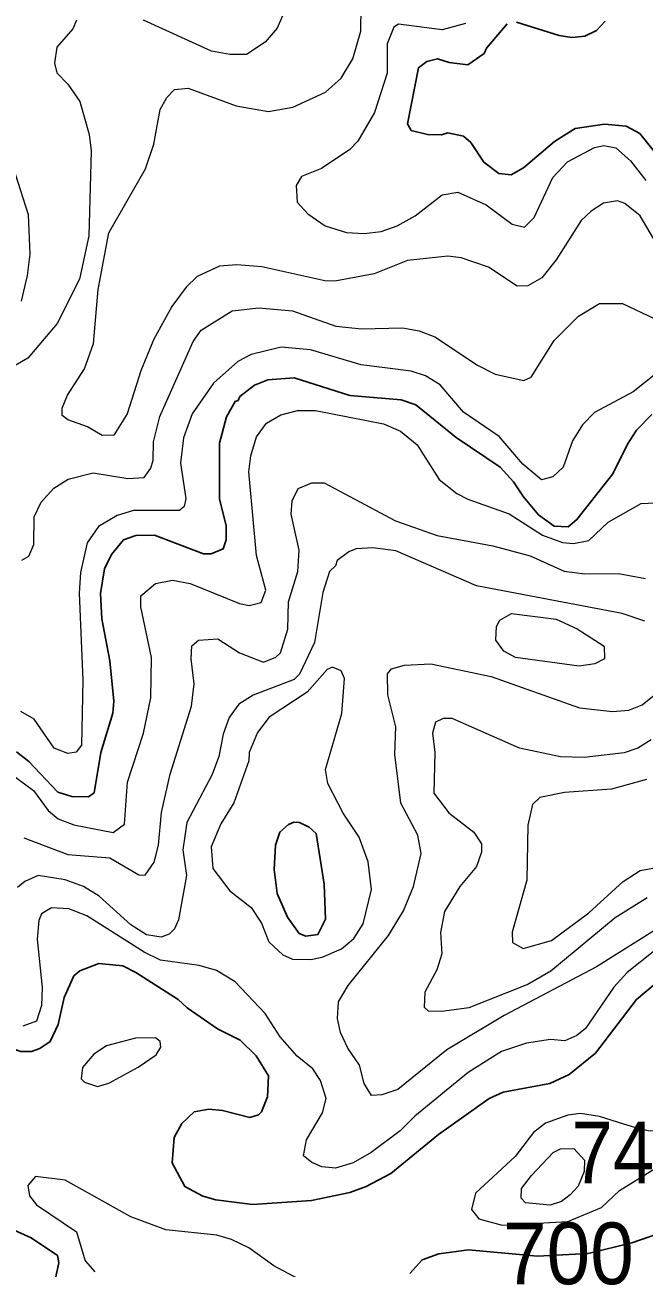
# Model space of a CAD drawing. Extents: x 673.3 to 698.5, y 6984.3 to 7012.3.
# Drawn here: x 674.508 to 675.31, y 6990.452 to 6992.064 of the extents above; entities that cross this region are included whole.
import ezdxf
from ezdxf.enums import TextEntityAlignment as Align

# ---------------------------------------------------------------- set-up
doc = ezdxf.new("R2010")
doc.units = 0
doc.header["$LTSCALE"] = 0.032
doc.layers.add('1', color=7, linetype='Continuous', lineweight=25)
doc.layers.add('2', color=7, linetype='Continuous', lineweight=13)
doc.layers.add('21', color=7, linetype='Continuous')
doc.layers.add('61', color=7, linetype='Continuous')

msp = doc.modelspace()

# ---------------------------------------------------------------- linework, layer by layer
at = {"layer": '1'}
for points in [[(675.1447, 6992.0675), (675.2002, 6992.05), (675.2165, 6992.0476), (675.2334, 6992.0493), (675.2485, 6992.0565), (675.2599, 6992.0686)], [(675.3485, 6991.8686), (675.3048, 6991.9228), (675.2868, 6991.9326), (675.2588, 6991.9351), (675.2211, 6991.9295), (675.1943, 6991.9125), (675.1538, 6991.8786), (675.1379, 6991.8692), (675.1221, 6991.871), (675.1027, 6991.8857), (675.0856, 6991.9115), (675.0764, 6991.9197), (675.0558, 6991.9237), (675.0477, 6991.9213), (675.0298, 6991.9215), (675.0086, 6991.9269), (675.0036, 6991.9357), (675.0181, 6992.0082), (675.0287, 6992.0162), (675.0425, 6992.0198), (675.0576, 6992.015), (675.0818, 6992.0119), (675.1028, 6992.0266), (675.1061, 6992.0336), (675.1328, 6992.0651)], [(674.622, 6991.1715), (674.623, 6991.187), (674.6182, 6991.2396), (674.6076, 6991.2937), (674.6061, 6991.3267), (674.611, 6991.3585), (674.6203, 6991.3774), (674.6356, 6991.3962), (674.6517, 6991.4017), (674.676, 6991.4025), (674.7395, 6991.3781), (674.7493, 6991.3781), (674.7649, 6991.3848), (674.7688, 6991.3961), (674.7688, 6991.4145), (674.76, 6991.4494), (674.76, 6991.5217), (674.769, 6991.5559), (674.7802, 6991.5757), (674.7842, 6991.5769), (674.7863, 6991.5819), (674.8055, 6991.5969), (674.8229, 6991.6037), (674.8568, 6991.6061), (674.9288, 6991.5833), (674.9956, 6991.5778), (675.0143, 6991.5714), (675.0667, 6991.5289), (675.1239, 6991.4904), (675.1412, 6991.4716), (675.1538, 6991.4518), (675.1734, 6991.4288), (675.1939, 6991.4139), (675.2119, 6991.4132), (675.2232, 6991.4226), (675.2699, 6991.4817), (675.2888, 6991.5204), (675.3003, 6991.5383), (675.3203, 6991.5588)], [(674.4969, 6991.1215), (674.5129, 6991.1088), (674.5505, 6991.0692), (674.5688, 6991.0637), (674.5905, 6991.063), (674.5976, 6991.0685), (674.6063, 6991.1205), (674.622, 6991.1715)], [(675.3569, 6990.8479), (675.3004, 6990.8004), (675.2471, 6990.7309), (675.2133, 6990.7034), (675.1879, 6990.6915), (675.1275, 6990.6802), (675.1096, 6990.6722), (675.0439, 6990.6252), (674.982, 6990.575), (674.9503, 6990.5582), (674.9288, 6990.5503), (674.8793, 6990.54), (674.8028, 6990.5345), (674.7552, 6990.5406), (674.7383, 6990.5455), (674.7154, 6990.5578), (674.6989, 6990.5889), (674.7012, 6990.6216), (674.7114, 6990.6396), (674.7271, 6990.6547), (674.7461, 6990.6581), (674.764, 6990.6565), (674.7995, 6990.6476), (674.8105, 6990.651), (674.8144, 6990.655), (674.8225, 6990.6741), (674.8234, 6990.7013), (674.8076, 6990.7276), (674.7867, 6990.7479), (674.7574, 6990.7624), (674.7182, 6990.7894), (674.7064, 6990.8002), (674.6519, 6990.8356), (674.635, 6990.8439), (674.6036, 6990.8471), (674.579, 6990.8376), (674.5714, 6990.831), (674.5587, 6990.8029), (674.5511, 6990.7682), (674.5405, 6990.746), (674.5272, 6990.7369), (674.5164, 6990.7331)], [(674.5164, 6990.7331), (674.5026, 6990.7331), (674.4804, 6990.7406), (674.4395, 6990.7608), (674.4056, 6990.7689), (674.3745, 6990.7681), (674.3636, 6990.7633), (674.3458, 6990.737), (674.3382, 6990.7184), (674.3391, 6990.6945), (674.3597, 6990.6728), (674.3742, 6990.6654), (674.4138, 6990.6572), (674.4224, 6990.6471), (674.426, 6990.6101), (674.4204, 6990.5589), (674.4387, 6990.5308), (674.4679, 6990.5131), (674.5162, 6990.4914), (674.5502, 6990.4687), (674.5521, 6990.4591), (674.5425, 6990.4155)], [(675.0069, 6990.4451), (675.0225, 6990.4628), (675.0444, 6990.4709), (675.0829, 6990.4757), (675.1719, 6990.4678), (675.2379, 6990.4713), (675.2942, 6990.4849), (675.343, 6990.502), (675.3637, 6990.5093), (675.3905, 6990.5282), (675.4394, 6990.5722), (675.467, 6990.5902), (675.5018, 6990.6036), (675.5396, 6990.602)]]:
    msp.add_lwpolyline(points, dxfattribs=at)
msp.add_lwpolyline([(674.8852, 6991.0156), (674.8763, 6991.0238), (674.8639, 6991.03), (674.8563, 6991.0303), (674.8493, 6991.0273), (674.8382, 6991.0173), (674.8325, 6991.0005), (674.8308, 6990.9689), (674.8347, 6990.9378), (674.8481, 6990.9071), (674.8635, 6990.8861), (674.8718, 6990.8823), (674.8877, 6990.8846), (674.8975, 6990.9044), (674.8959, 6990.9501)], close=True, dxfattribs=at)
at = {"layer": '2'}
for points in [[(674.658, 6991.6155), (674.6404, 6991.5594), (674.6231, 6991.5321), (674.6083, 6991.5313), (674.5891, 6991.5429), (674.5637, 6991.5516), (674.5564, 6991.5576), (674.5564, 6991.567), (674.5632, 6991.584), (674.585, 6991.6178), (674.5968, 6991.6507), (674.6028, 6991.7207), (674.6168, 6991.7944), (674.6641, 6991.877), (674.6752, 6991.909), (674.6832, 6991.954), (674.6919, 6991.9696), (674.7016, 6991.98), (674.7197, 6991.9816), (674.7816, 6991.9588), (674.8236, 6991.9514), (674.8552, 6991.957), (674.8975, 6991.9767), (674.9179, 6991.9945), (674.9327, 6992.0198), (674.9431, 6992.0556), (674.9438, 6992.0872)], [(674.8486, 6992.0914), (674.835, 6992.0595), (674.8191, 6992.0414), (674.7952, 6992.0256), (674.7737, 6992.0254), (674.7499, 6992.0299), (674.6617, 6992.0701)], [(674.575, 6992.07), (674.5699, 6992.0587), (674.5493, 6992.0348), (674.5465, 6992.0143), (674.5493, 6992.0017), (674.5638, 6991.987), (674.5791, 6991.9644), (674.5914, 6991.9218), (674.5937, 6991.9006), (674.5907, 6991.7903), (674.5787, 6991.7343), (674.5498, 6991.6768), (674.5118, 6991.6317), (674.4643, 6991.6045)], [(674.986, 6992.0609), (674.9774, 6992.0393), (674.9773, 6992.0013), (674.9608, 6991.9502), (674.9395, 6991.9129), (674.9289, 6991.9023), (674.8921, 6991.8778), (674.8665, 6991.8672), (674.8593, 6991.8557), (674.8608, 6991.834), (674.8745, 6991.8189), (674.8968, 6991.8033), (674.9248, 6991.7948), (674.9476, 6991.7934), (674.9696, 6991.7959), (674.9903, 6991.8031), (675.0135, 6991.8163), (675.0484, 6991.8435), (675.069, 6991.8471), (675.1054, 6991.8304), (675.1391, 6991.8054), (675.1554, 6991.8016), (675.1678, 6991.8143), (675.1919, 6991.8661), (675.211, 6991.8862), (675.2461, 6991.9049), (675.2582, 6991.9073), (675.2735, 6991.9042), (675.2926, 6991.8876), (675.3126, 6991.8621)], [(675.0787, 6992.0655), (675.0485, 6992.0573), (674.9919, 6992.0645), (674.986, 6992.0609)], [(674.5034, 6991.7057), (674.5114, 6991.739), (674.5147, 6991.7667), (674.5127, 6991.8177), (674.4959, 6991.8702)], [(675.3226, 6991.7869), (675.3053, 6991.8164), (675.2851, 6991.8324), (675.2757, 6991.8356), (675.2578, 6991.8325), (675.2418, 6991.8225), (675.2289, 6991.8102), (675.1963, 6991.7594), (675.1779, 6991.7358), (675.1595, 6991.7257), (675.1458, 6991.7251), (675.1087, 6991.7497), (675.0733, 6991.762), (675.0561, 6991.764), (675.0038, 6991.7584), (674.9605, 6991.7411), (674.9096, 6991.7316), (674.8964, 6991.732), (674.8148, 6991.7502), (674.7825, 6991.7526), (674.7602, 6991.751), (674.731, 6991.7376), (674.717, 6991.7238), (674.6982, 6991.6987), (674.6744, 6991.6557), (674.658, 6991.6155)], [(674.5039, 6991.3701), (674.5132, 6991.3752), (674.5195, 6991.3901), (674.5198, 6991.4261), (674.529, 6991.4449), (674.5453, 6991.4632), (674.5639, 6991.475), (674.5965, 6991.4832), (674.6415, 6991.4758), (674.6627, 6991.4772), (674.6712, 6991.4891), (674.6742, 6991.4997), (674.6744, 6991.5234), (674.6828, 6991.5562), (674.7258, 6991.6533), (674.7363, 6991.668), (674.7764, 6991.6929), (674.8112, 6991.6972), (674.8547, 6991.6929), (674.9107, 6991.6733), (674.9439, 6991.6696), (674.9973, 6991.6712), (675.019, 6991.6673), (675.039, 6991.6592), (675.0944, 6991.6225), (675.1171, 6991.6111), (675.1542, 6991.6029), (675.1639, 6991.6072), (675.1938, 6991.6547), (675.2252, 6991.6862), (675.2525, 6991.7025), (675.2821, 6991.7027), (675.3243, 6991.6827)], [(675.2175, 6991.5244), (675.2052, 6991.4903), (675.192, 6991.4781), (675.1775, 6991.4742), (675.1532, 6991.4945), (675.1223, 6991.5303), (675.0764, 6991.5617), (675.0462, 6991.5973), (675.0272, 6991.6089), (675.0086, 6991.615), (674.9435, 6991.6232), (674.878, 6991.6427), (674.8401, 6991.646), (674.8013, 6991.6367), (674.7838, 6991.6274), (674.7524, 6991.5993), (674.7249, 6991.5596), (674.7136, 6991.5286), (674.7095, 6991.4956), (674.7167, 6991.4497), (674.7143, 6991.4394), (674.7083, 6991.4343), (674.6487, 6991.4342), (674.6275, 6991.4278), (674.6033, 6991.4136), (674.5886, 6991.3922), (674.58, 6991.3539), (674.5783, 6991.3271), (674.5831, 6991.2142), (674.5815, 6991.13), (674.5742, 6991.1212), (674.5634, 6991.1192), (674.546, 6991.1264), (674.5198, 6991.1636), (674.5028, 6991.1739)], [(675.3255, 6991.6114), (675.296, 6991.5883), (675.2461, 6991.5612), (675.2305, 6991.5452), (675.2175, 6991.5244)], [(674.4959, 6991.0887), (674.5191, 6991.0715), (674.538, 6991.0452), (674.5511, 6991.0348), (674.5712, 6991.0267), (674.6224, 6991.0167), (674.637, 6991.0277), (674.6411, 6991.082), (674.6618, 6991.1456), (674.6712, 6991.1914), (674.672, 6991.2438), (674.6582, 6991.3093), (674.6583, 6991.3236), (674.6772, 6991.3398), (674.6992, 6991.3438), (674.7219, 6991.3396), (674.7861, 6991.3139), (674.7986, 6991.3113), (674.8139, 6991.315), (674.82, 6991.3312), (674.808, 6991.3761), (674.7982, 6991.4844), (674.8006, 6991.5051), (674.808, 6991.5297), (674.8211, 6991.5476), (674.8396, 6991.5583), (674.8612, 6991.5637), (674.8845, 6991.5637), (674.9728, 6991.5465), (674.9947, 6991.5371), (675.0162, 6991.5192), (675.0447, 6991.4744), (675.0675, 6991.4564), (675.0819, 6991.4488), (675.1356, 6991.43), (675.1786, 6991.4025), (675.2044, 6991.3926), (675.2189, 6991.3914), (675.2385, 6991.3952), (675.2635, 6991.4191), (675.3065, 6991.4432), (675.3335, 6991.4446)], [(674.5064, 6991.0098), (674.5637, 6990.9883), (674.6182, 6990.9839), (674.6558, 6990.9621), (674.6637, 6990.9616), (674.6753, 6990.9785), (674.6809, 6991.0003), (674.685, 6991.0428), (674.6964, 6991.0926), (674.724, 6991.1807), (674.7274, 6991.2098), (674.7233, 6991.2422), (674.7241, 6991.2588), (674.7329, 6991.2662), (674.758, 6991.2681), (674.7862, 6991.2496), (674.8172, 6991.2379), (674.8329, 6991.2443), (674.8392, 6991.2498), (674.8486, 6991.2803), (674.8494, 6991.3159), (674.8617, 6991.3552), (674.8633, 6991.3829), (674.8528, 6991.4295), (674.8541, 6991.447), (674.8622, 6991.463), (674.8799, 6991.4701), (674.8956, 6991.47), (674.9881, 6991.4207), (675.0422, 6991.4017), (675.1142, 6991.3886), (675.1627, 6991.3757), (675.2065, 6991.3558), (675.2336, 6991.352), (675.277, 6991.3528), (675.3119, 6991.346)], [(675.3113, 6991.2909), (675.2816, 6991.3007), (675.0931, 6991.3366), (674.9887, 6991.3821), (674.9587, 6991.3861), (674.9373, 6991.3846), (674.9278, 6991.3809), (674.9126, 6991.3693), (674.9103, 6991.3625), (674.9026, 6991.3552), (674.894, 6991.3281), (674.883, 6991.2631), (674.8638, 6991.2223), (674.857, 6991.2154), (674.8037, 6991.195), (674.7852, 6991.1834), (674.7728, 6991.166), (674.765, 6991.1445), (674.7594, 6991.1154), (674.7504, 6991.0921), (674.7177, 6991.0298), (674.7127, 6990.9946), (674.7175, 6990.9611), (674.7068, 6990.9038), (674.7019, 6990.8919), (674.6951, 6990.8849), (674.6847, 6990.8812), (674.6654, 6990.8843), (674.6454, 6990.8973), (674.6042, 6990.9344), (674.5839, 6990.9469), (674.5601, 6990.9554), (674.525, 6990.961), (674.5081, 6990.9535), (674.4986, 6990.9456)], [(674.995, 6991.055), (674.9872, 6991.118), (674.9887, 6991.1538), (674.9782, 6991.1953), (674.9776, 6991.2225), (674.9831, 6991.2289), (674.9996, 6991.234), (675.034, 6991.2356), (675.112, 6991.2189), (675.2265, 6991.1785), (675.2693, 6991.1737), (675.2906, 6991.1753), (675.3078, 6991.1825), (675.3277, 6991.1984)], [(675.3194, 6991.1371), (675.302, 6991.1263), (675.2842, 6991.12), (675.2324, 6991.1142), (675.2018, 6991.1151), (675.1487, 6991.1263), (675.0617, 6991.1646), (675.0501, 6991.1646), (675.0398, 6991.1601), (675.0359, 6991.1456), (675.0392, 6991.1204), (675.0377, 6991.068), (675.0571, 6991.0425), (675.0895, 6991.0175), (675.0995, 6991.0023), (675.0996, 6990.9912), (675.0929, 6990.9726), (675.0716, 6990.947), (675.0517, 6990.9145), (675.0466, 6990.8872), (675.048, 6990.8595), (675.0417, 6990.839), (675.0263, 6990.8101), (675.0254, 6990.7904), (675.0303, 6990.7859), (675.0479, 6990.7855), (675.0837, 6990.7902), (675.1589, 6990.8198), (675.1894, 6990.8375), (675.2726, 6990.9069), (675.314, 6990.9327)], [(675.3135, 6991.0858), (675.2678, 6991.0732), (675.2073, 6991.0687), (675.1751, 6991.0623), (675.1657, 6991.0532)], [(675.3503, 6990.9065), (675.2484, 6990.8426), (675.1291, 6990.7796), (675.0545, 6990.735), (674.991, 6990.6837), (674.9705, 6990.6768), (674.9571, 6990.6761), (674.9475, 6990.6917), (674.9415, 6990.7153), (674.9262, 6990.7374), (674.9169, 6990.7578), (674.9131, 6990.7759), (674.9145, 6990.7975), (674.9269, 6990.8185), (674.9791, 6990.8832), (674.9984, 6990.9154), (675.0116, 6990.9467), (675.0212, 6990.9897), (675.0171, 6991.0135), (674.995, 6991.055)], [(675.1657, 6991.0532), (675.1598, 6991.0265), (675.1582, 6990.9553), (675.1395, 6990.8878), (675.1398, 6990.8745), (675.1535, 6990.8667), (675.1901, 6990.877), (675.2385, 6990.9128), (675.283, 6990.9533), (675.3051, 6990.9676), (675.3451, 6990.9749)], [(674.565, 6990.918), (674.5423, 6990.9193), (674.5295, 6990.9113), (674.5261, 6990.9029), (674.5238, 6990.8785), (674.5302, 6990.8158), (674.5293, 6990.7926), (674.5231, 6990.7723), (674.5051, 6990.7658)], [(675.3243, 6990.8641), (675.2881, 6990.8353), (675.2709, 6990.8163), (675.2343, 6990.763), (675.2231, 6990.7539), (675.2075, 6990.747), (675.1891, 6990.7485), (675.1578, 6990.7436), (675.1255, 6990.7329), (675.0822, 6990.7058), (675.0132, 6990.6491), (674.9942, 6990.6303), (674.9565, 6990.6021), (674.9331, 6990.5888), (674.9106, 6990.5816), (674.8929, 6990.5833), (674.8797, 6990.589), (674.8691, 6990.5977), (674.8729, 6990.6183), (674.8935, 6990.6534), (674.8982, 6990.6722), (674.891, 6990.6956), (674.881, 6990.7105), (674.8606, 6990.7268), (674.8386, 6990.752), (674.8191, 6990.7822), (674.7805, 6990.8232), (674.7561, 6990.838), (674.7337, 6990.8445), (674.6837, 6990.8512), (674.6623, 6990.8619), (674.5881, 6990.9089), (674.565, 6990.918)], [(674.901, 6990.4174), (674.8305, 6990.455), (674.798, 6990.4783), (674.7757, 6990.4894), (674.7565, 6990.4951), (674.6904, 6990.5018), (674.6451, 6990.5189), (674.5602, 6990.5661), (674.5217, 6990.571), (674.5117, 6990.5591), (674.5139, 6990.546), (674.5231, 6990.5342), (674.575, 6990.4992), (674.5862, 6990.4618), (674.5987, 6990.4474)]]:
    msp.add_lwpolyline(points, dxfattribs=at)
for points in [[(675.1438, 6991.2439), (675.1283, 6991.2518), (675.1183, 6991.266), (675.1191, 6991.2839), (675.1232, 6991.2923), (675.1384, 6991.3006), (675.1964, 6991.2935), (675.2236, 6991.281), (675.2587, 6991.2585), (675.259, 6991.2421), (675.2462, 6991.2356), (675.2263, 6991.2323)], [(674.9187, 6991.1713), (674.922, 6991.2163), (674.9176, 6991.2265), (674.9063, 6991.2313), (674.8998, 6991.228), (674.8737, 6991.1988), (674.8245, 6991.1665), (674.8094, 6991.1465), (674.7986, 6991.1207), (674.7981, 6991.1097), (674.7785, 6991.0554), (674.7617, 6991.0282), (674.7493, 6990.9982), (674.7514, 6990.9703), (674.7736, 6990.9411), (674.801, 6990.9196), (674.8144, 6990.8992), (674.8241, 6990.8752), (674.8421, 6990.8585), (674.8547, 6990.8526), (674.8785, 6990.8523), (674.8932, 6990.8555), (674.9181, 6990.8663), (674.9342, 6990.8796), (674.9461, 6990.8986), (674.9569, 6990.9429), (674.9529, 6990.979), (674.941, 6991.011), (674.9202, 6991.042), (674.9006, 6991.0803), (674.8975, 6991.0984)], [(674.6546, 6990.7126), (674.6782, 6990.7288), (674.684, 6990.7385), (674.6832, 6990.7461), (674.6773, 6990.7509), (674.6513, 6990.7501), (674.6139, 6990.7402), (674.5974, 6990.7294), (674.5825, 6990.7122), (674.5807, 6990.6974), (674.585, 6990.6931), (674.6019, 6990.6875), (674.6168, 6990.6921)], [(675.2784, 6990.5527), (675.3235, 6990.5807), (675.366, 6990.5919), (675.3756, 6990.5971), (675.3838, 6990.6059), (675.3844, 6990.6215), (675.375, 6990.6298), (675.3652, 6990.6319), (675.3266, 6990.6297), (675.3154, 6990.6303), (675.3024, 6990.6334), (675.2841, 6990.6386), (675.2524, 6990.6486), (675.2278, 6990.6527), (675.2116, 6990.6506), (675.1825, 6990.64), (675.167, 6990.6278), (675.1432, 6990.5968), (675.0916, 6990.5493), (675.0864, 6990.5283), (675.0961, 6990.5161), (675.1264, 6990.5078), (675.2113, 6990.5126), (675.2551, 6990.5306)], [(675.1923, 6990.6019), (675.202, 6990.6069), (675.2192, 6990.6073), (675.2329, 6990.5922), (675.2326, 6990.5773), (675.2247, 6990.5585), (675.2144, 6990.5472), (675.203, 6990.5387), (675.1885, 6990.5338), (675.1566, 6990.5369), (675.151, 6990.5429), (675.1515, 6990.5554), (675.1645, 6990.5723)]]:
    msp.add_lwpolyline(points, close=True, dxfattribs=at)

# ---------------------------------------------------------------- texts
at = {"layer": '21', "width": 0.9}
msp.add_text('741', height=0.08, dxfattribs=at).set_placement((675.2162, 6990.5621))
at = {"layer": '61', "width": 0.95}
msp.add_text('700', height=0.08, dxfattribs=at).set_placement((675.2122, 6990.4313), align=Align.CENTER)

doc.saveas('drawing.dxf')
